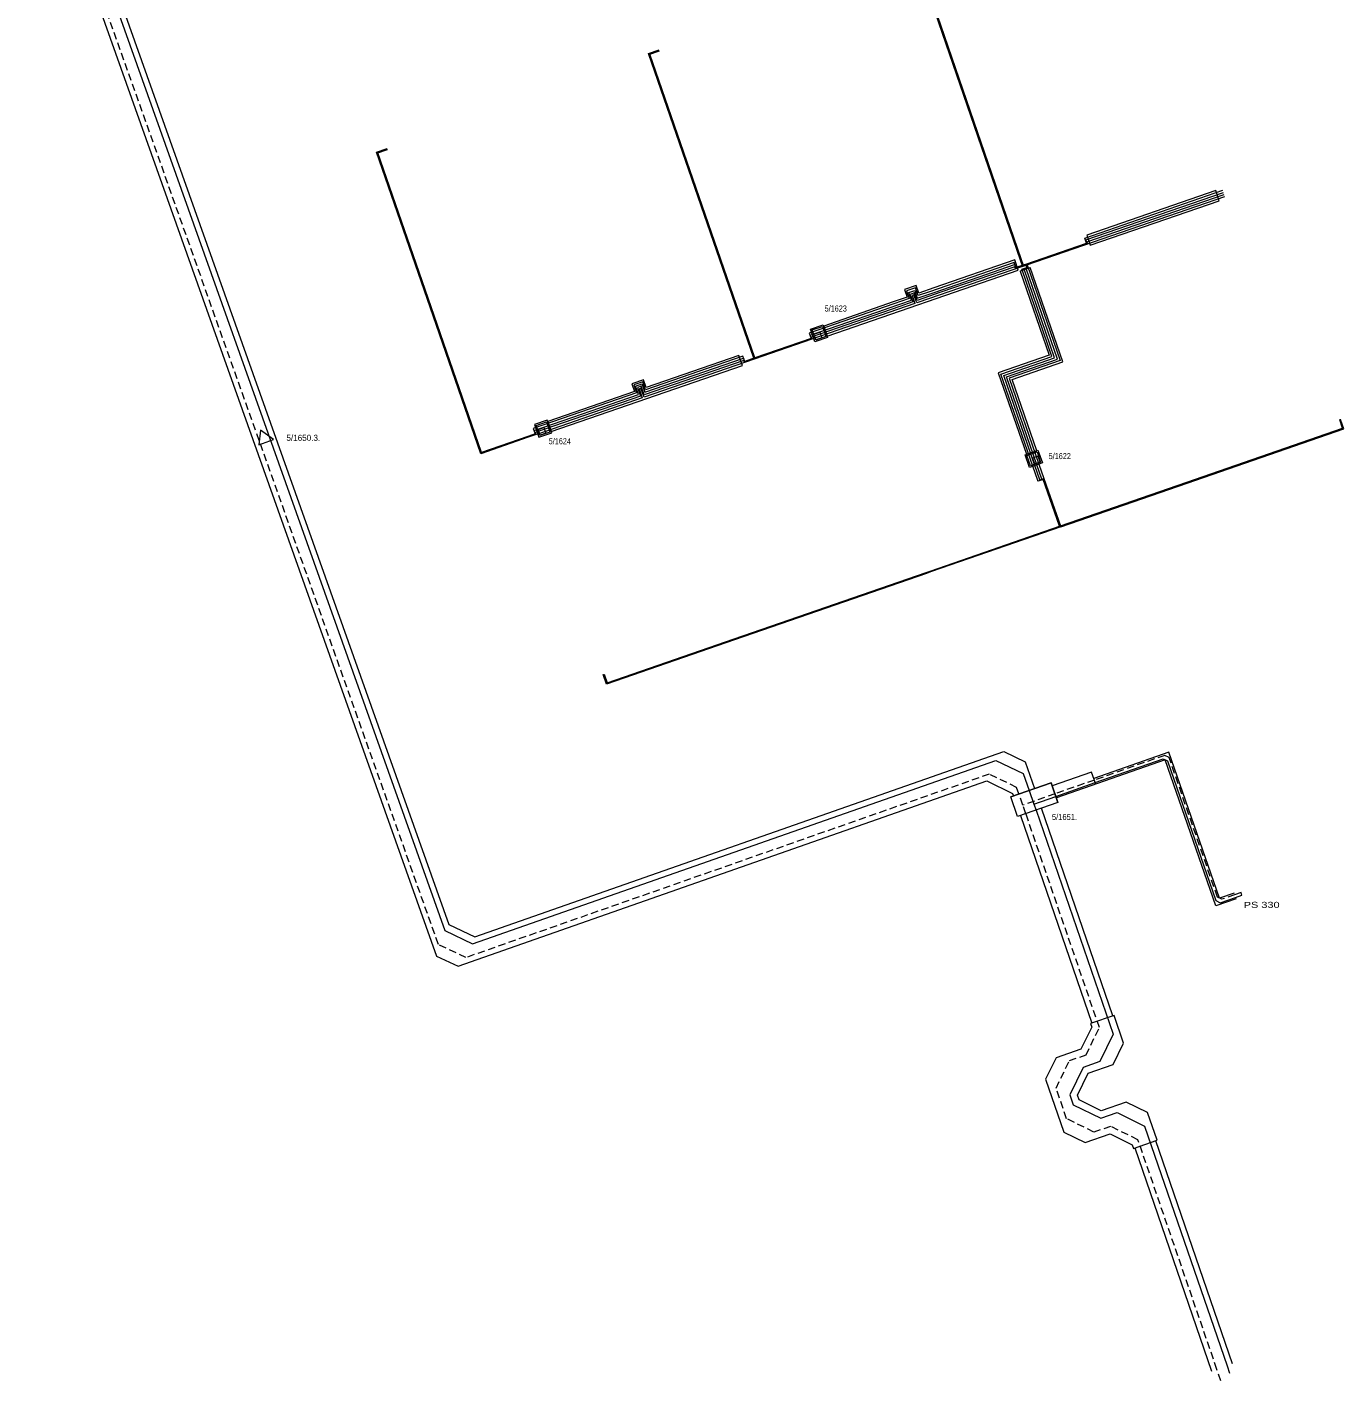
# Model space of a CAD drawing. Extents: x -473467 to -473049, y -1106745 to -1106181.
# Drawn here: x -473244.9 to -473049.3, y -1106744.6 to -1106543.7 of the extents above; entities that cross this region are included whole.
import ezdxf
from ezdxf.enums import TextEntityAlignment as Align

# ---------------------------------------------------------------- set-up
doc = ezdxf.new("R2010")
doc.units = 0
doc.header["$LTSCALE"] = 0.36
doc.linetypes.add('MEDIUM_DASHED', pattern=[4.5, 3, -1.5])
for name, color, linetype, lineweight in [('1', 7, 'MEDIUM_DASHED', 13), ('11', 7, 'Continuous', 13), ('14', 7, 'Continuous', 13), ('15', 7, 'Continuous', 13), ('17', 7, 'Continuous', 13), ('4', 7, 'Continuous', 13), ('7', 7, 'Continuous', 13)]:
    doc.layers.add(name, color=color, linetype=linetype, lineweight=lineweight)
for name, color, linetype in [('16', 7, 'Continuous'), ('6', 7, 'Continuous'), ('9', 7, 'Continuous')]:
    doc.layers.add(name, color=color, linetype=linetype)

msp = doc.modelspace()

# ---------------------------------------------------------------- linework, layer by layer
at = {"layer": '1', "linetype": 'Continuous'}
for points in [[(-473246.013, -1106500.34), (-473245.619, -1106501.193), (-473182.812, -1106677.763), (-473178.72, -1106679.719), (-473101.034, -1106652.497), (-473096.956, -1106654.459), (-473096.08, -1106656.96), (-473095.369, -1106658.988)], [(-473086.246, -1106655.792), (-473076.18, -1106652.264), (-473075.545, -1106652.572), (-473068.36, -1106673.32), (-473067.724, -1106673.628), (-473065.428, -1106672.833), (-473064.483, -1106672.506)], [(-473095.369, -1106658.988), (-473092.113, -1106657.848), (-473086.246, -1106655.792)], [(-473095.369, -1106658.988), (-473095.053, -1106659.89), (-473083.609, -1106693.153), (-473085.594, -1106697.22), (-473088.053, -1106698.065), (-473090.038, -1106702.132), (-473089.517, -1106703.647), (-473085.45, -1106705.631), (-473082.991, -1106704.786), (-473078.924, -1106706.771), (-473066.675, -1106742.375), (-473066.31, -1106743.478)]]:
    msp.add_lwpolyline(points, dxfattribs=at)
at = {"layer": '1'}
for points in [[(-473097.014, -1106659.141), (-473097.592, -1106657.49), (-473097.935, -1106656.511), (-473102.013, -1106654.549), (-473179.701, -1106681.772), (-473183.794, -1106679.815), (-473247.114, -1106501.803), (-473247.258, -1106501.495)], [(-473064.483, -1106672.506), (-473064.614, -1106672.128), (-473065.559, -1106672.455), (-473067.477, -1106673.12), (-473068.113, -1106672.811), (-473075.298, -1106652.061), (-473075.934, -1106651.754), (-473086.378, -1106655.414)], [(-473086.378, -1106655.414), (-473092.245, -1106657.47), (-473097.014, -1106659.141)], [(-473067.624, -1106744.609), (-473068.19, -1106742.899), (-473079.919, -1106708.808), (-473083.986, -1106706.823), (-473086.444, -1106707.669), (-473090.511, -1106705.684), (-473092.075, -1106701.138), (-473090.09, -1106697.071), (-473087.631, -1106696.225), (-473085.646, -1106692.158), (-473096.568, -1106660.412), (-473097.014, -1106659.141)]]:
    msp.add_lwpolyline(points, dxfattribs=at)
at = {"layer": '11'}
for p, q in [((-473096.399, -1106578.95), (-473066.993, -1106568.795)), ((-473116.063, -1106585.063), (-473116.047, -1106585.057)), ((-473128.322, -1106589.991), (-473136.906, -1106592.958)), ((-473091.387, -1106617.854), (-473072.623, -1106611.36)), ((-473139.878, -1106634.476), (-473111.357, -1106624.606)), ((-473139.864, -1106634.524), (-473111.376, -1106624.665)), ((-473111.358, -1106624.712), (-473139.85, -1106634.572)), ((-473111.337, -1106624.758), (-473139.83, -1106634.618))]:
    msp.add_line(p, q, dxfattribs=at)
for points in [[(-473115.3, -1106526.116), (-473097.408, -1106578.227), (-473097.077, -1106579.184), (-473096.718, -1106579.06), (-473096.399, -1106578.95)], [(-473115.002, -1106525.997), (-473115.258, -1106526.085), (-473097.413, -1106578.06), (-473097.361, -1106578.211), (-473097.046, -1106579.121), (-473096.74, -1106579.015), (-473096.455, -1106578.916)], [(-473114.684, -1106525.941), (-473115.194, -1106526.116), (-473097.366, -1106578.043), (-473097.314, -1106578.195), (-473097.015, -1106579.057), (-473096.761, -1106578.969), (-473096.525, -1106578.888)], [(-473114.365, -1106525.884), (-473115.131, -1106526.147), (-473097.318, -1106578.027), (-473097.266, -1106578.178), (-473096.985, -1106578.993), (-473096.766, -1106578.918), (-473096.579, -1106578.853)], [(-473136.897, -1106592.955), (-473136.947, -1106592.81), (-473152.583, -1106547.586), (-473151.024, -1106547.047)], [(-473136.867, -1106592.888), (-473136.9, -1106592.793), (-473152.519, -1106547.617), (-473151.007, -1106547.094)], [(-473136.837, -1106592.824), (-473136.853, -1106592.777), (-473152.456, -1106547.648), (-473150.991, -1106547.142)], [(-473136.806, -1106592.761), (-473152.392, -1106547.679), (-473150.975, -1106547.189)], [(-473184.561, -1106586.506), (-473192.962, -1106562.209), (-473191.402, -1106561.669)], [(-473184.511, -1106586.497), (-473192.897, -1106562.24), (-473191.385, -1106561.717)], [(-473191.369, -1106561.764), (-473192.834, -1106562.271), (-473184.463, -1106586.484)], [(-473184.413, -1106586.474), (-473192.77, -1106562.302), (-473191.353, -1106561.811)], [(-473096.579, -1106578.853), (-473087.543, -1106575.733), (-473087.808, -1106574.968), (-473067.308, -1106567.889)], [(-473096.525, -1106578.888), (-473087.48, -1106575.764), (-473087.656, -1106575.254), (-473067.204, -1106568.191)], [(-473096.455, -1106578.916), (-473087.418, -1106575.796), (-473087.505, -1106575.54), (-473067.099, -1106568.494)], [(-473096.985, -1106578.993), (-473098.05, -1106579.361), (-473098.314, -1106578.596), (-473110.877, -1106582.933), (-473112.56, -1106583.515), (-473112.954, -1106582.377), (-473114.265, -1106582.831), (-473113.873, -1106583.968), (-473116.151, -1106584.756), (-473128.732, -1106589.099)], [(-473128.58, -1106589.385), (-473117.401, -1106585.525), (-473117.024, -1106585.395), (-473113.561, -1106584.198), (-473113.953, -1106583.064), (-473113.069, -1106582.758), (-473112.676, -1106583.892), (-473111.055, -1106583.332), (-473110.033, -1106582.981), (-473098.257, -1106578.914), (-473098.081, -1106579.425), (-473097.015, -1106579.057)], [(-473097.046, -1106579.121), (-473098.112, -1106579.488), (-473098.2, -1106579.233), (-473109.189, -1106583.028), (-473112.685, -1106584.234), (-473113.077, -1106583.1), (-473113.735, -1106583.327), (-473113.34, -1106584.46), (-473115.251, -1106585.121), (-473128.428, -1106589.671)], [(-473097.077, -1106579.184), (-473112.578, -1106584.544), (-473112.766, -1106584.609), (-473113.186, -1106583.397), (-473113.465, -1106583.493), (-473113.036, -1106584.708), (-473128.322, -1106589.991)], [(-473094.757, -1106611.051), (-473094.773, -1106611.004), (-473094.79, -1106610.957), (-473095.519, -1106608.848), (-473100.258, -1106595.156), (-473092.697, -1106592.539), (-473097.124, -1106579.705), (-473097.156, -1106579.611), (-473096.395, -1106579.348), (-473096.567, -1106578.849)], [(-473094.471, -1106610.899), (-473094.487, -1106610.852), (-473095.217, -1106608.744), (-473099.851, -1106595.353), (-473092.29, -1106592.737), (-473096.824, -1106579.602), (-473096.84, -1106579.554), (-473096.332, -1106579.379), (-473096.504, -1106578.88)], [(-473094.185, -1106610.747), (-473094.914, -1106608.639), (-473099.444, -1106595.551), (-473091.884, -1106592.935), (-473096.524, -1106579.498), (-473096.268, -1106579.41), (-473096.44, -1106578.911)], [(-473096.377, -1106578.942), (-473091.477, -1106593.133), (-473099.037, -1106595.749), (-473094.612, -1106608.534), (-473093.882, -1106610.643)], [(-473169.289, -1106604.151), (-473170.443, -1106604.55), (-473177.481, -1106606.983), (-473184.561, -1106586.506)], [(-473169.309, -1106604.104), (-473170.46, -1106604.502), (-473177.45, -1106606.919), (-473184.511, -1106586.497)], [(-473184.463, -1106586.484), (-473177.419, -1106606.855), (-473170.476, -1106604.455), (-473169.373, -1106604.073)], [(-473169.436, -1106604.042), (-473170.492, -1106604.407), (-473177.388, -1106606.792), (-473184.413, -1106586.474)], [(-473128.428, -1106589.671), (-473128.336, -1106589.938), (-473136.87, -1106592.889)], [(-473136.843, -1106592.826), (-473128.399, -1106589.907), (-473128.58, -1106589.385)], [(-473128.732, -1106589.099), (-473128.463, -1106589.876), (-473136.809, -1106592.762)], [(-473136.809, -1106592.762), (-473138.293, -1106593.275), (-473138.562, -1106592.494), (-473153.043, -1106597.495), (-473153.455, -1106596.301), (-473154.778, -1106596.761), (-473154.366, -1106597.951), (-473169.71, -1106603.25), (-473169.436, -1106604.042)], [(-473169.373, -1106604.073), (-473169.558, -1106603.536), (-473154.073, -1106598.189), (-473154.503, -1106596.942), (-473153.558, -1106596.616), (-473153.128, -1106597.862), (-473138.505, -1106592.813), (-473138.324, -1106593.338), (-473136.843, -1106592.826)], [(-473136.87, -1106592.889), (-473138.355, -1106593.402), (-473138.448, -1106593.132), (-473153.212, -1106598.23), (-473153.659, -1106596.936), (-473154.226, -1106597.132), (-473153.779, -1106598.426), (-473169.407, -1106603.822), (-473169.309, -1106604.104)], [(-473136.906, -1106592.958), (-473153.241, -1106598.604), (-473153.715, -1106597.233), (-473153.999, -1106597.331), (-473153.525, -1106598.702), (-473169.025, -1106604.059), (-473169.289, -1106604.151)], [(-473072.623, -1106611.36), (-473049.334, -1106603.301), (-473049.824, -1106601.883)], [(-473072.669, -1106611.217), (-473049.525, -1106603.208), (-473049.966, -1106601.932)], [(-473072.656, -1106611.266), (-473049.461, -1106603.239), (-473049.919, -1106601.916)], [(-473072.638, -1106611.313), (-473049.397, -1106603.27), (-473049.872, -1106601.899)], [(-473111.376, -1106624.665), (-473110.598, -1106624.396), (-473091.514, -1106617.792), (-473093.961, -1106610.723), (-473094.471, -1106610.899)], [(-473094.185, -1106610.747), (-473093.93, -1106610.659), (-473093.93, -1106610.659), (-473091.45, -1106617.823), (-473110.575, -1106624.441), (-473111.358, -1106624.712)], [(-473111.357, -1106624.606), (-473110.613, -1106624.348), (-473091.578, -1106617.761), (-473093.991, -1106610.786), (-473094.757, -1106611.051)], [(-473093.882, -1106610.643), (-473091.387, -1106617.854), (-473110.562, -1106624.489), (-473111.337, -1106624.758)], [(-473091.578, -1106617.761), (-473091.436, -1106617.712), (-473072.669, -1106611.217)], [(-473091.514, -1106617.792), (-473091.42, -1106617.759), (-473072.656, -1106611.266)], [(-473091.45, -1106617.823), (-473091.403, -1106617.806), (-473072.638, -1106611.313)], [(-473139.83, -1106634.618), (-473158.826, -1106641.192), (-473159.317, -1106639.774)], [(-473139.85, -1106634.572), (-473158.796, -1106641.128), (-473159.27, -1106639.758)], [(-473159.223, -1106639.742), (-473158.765, -1106641.065), (-473139.864, -1106634.524)], [(-473159.175, -1106639.725), (-473158.734, -1106641.001), (-473139.878, -1106634.476)]]:
    msp.add_lwpolyline(points, dxfattribs=at)
at = {"layer": '14'}
for points in [[(-473126.765, -1106588.094), (-473126.245, -1106589.607), (-473127.757, -1106590.13), (-473128.279, -1106588.618), (-473126.762, -1106588.093)], [(-473169.255, -1106602.784), (-473167.739, -1106602.261), (-473167.219, -1106603.763), (-473168.728, -1106604.294), (-473169.255, -1106602.784)], [(-473095.878, -1106608.761), (-473096.401, -1106607.249), (-473094.889, -1106606.726), (-473094.366, -1106608.238)]]:
    msp.add_lwpolyline(points, close=True, dxfattribs=at)
at = {"layer": '15'}
for points in [[(-473128.02, -1106589.216), (-473127.17, -1106588.922), (-473126.876, -1106589.772), (-473127.726, -1106590.067), (-473128.02, -1106589.216)], [(-473168.697, -1106604.23), (-473168.996, -1106603.382), (-473168.147, -1106603.083), (-473167.848, -1106603.931)], [(-473094.43, -1106608.207), (-473094.724, -1106607.356), (-473095.574, -1106607.651), (-473095.28, -1106608.501)]]:
    msp.add_lwpolyline(points, close=True, dxfattribs=at)
at = {"layer": '17'}
for points in [[(-473087.006, -1106576.041), (-473067.836, -1106569.425), (-473068.358, -1106567.913), (-473087.528, -1106574.528)], [(-473116.253, -1106584.46), (-473126.579, -1106588.03), (-473126.056, -1106589.542), (-473097.681, -1106579.732), (-473098.204, -1106578.219), (-473110.241, -1106582.381), (-473112.474, -1106583.153), (-473112.867, -1106582.019), (-473114.568, -1106582.607), (-473114.176, -1106583.742)], [(-473127.881, -1106590.385), (-473128.534, -1106588.494), (-473126.644, -1106587.841), (-473125.991, -1106589.731)], [(-473138.857, -1106593.227), (-473139.163, -1106592.381), (-473152.951, -1106597.148), (-473153.343, -1106596.014), (-473155.045, -1106596.602), (-473154.653, -1106597.736), (-473167.558, -1106602.197), (-473167.026, -1106603.707), (-473138.62, -1106593.886)], [(-473168.85, -1106604.549), (-473166.964, -1106603.885), (-473167.628, -1106601.998), (-473169.514, -1106602.663)], [(-473096.656, -1106607.125), (-473094.766, -1106606.471), (-473094.112, -1106608.361), (-473096.002, -1106609.015)]]:
    msp.add_lwpolyline(points, close=True, dxfattribs=at)
for points in [[(-473097.409, -1106579.873), (-473097.409, -1106579.873), (-473093.093, -1106592.347), (-473100.653, -1106594.964), (-473096.466, -1106607.06), (-473094.955, -1106606.537), (-473098.617, -1106595.952), (-473091.057, -1106593.336), (-473095.897, -1106579.35), (-473095.897, -1106579.35)], [(-473096.653, -1106579.612), (-473097.409, -1106579.873), (-473096.653, -1106579.612), (-473095.897, -1106579.35)]]:
    msp.add_lwpolyline(points, dxfattribs=at)
at = {"layer": '4'}
for points in [[(-473210.471, -1106605.678), (-473208.253, -1106604.885), (-473210.201, -1106603.476)], [(-473098.816, -1106657.919), (-473092.823, -1106655.819), (-473091.798, -1106658.745), (-473097.791, -1106660.845)]]:
    msp.add_lwpolyline(points, close=True, dxfattribs=at)
at = {"layer": '7'}
for p, q in [((-473092.823, -1106655.819), (-473098.816, -1106657.919)), ((-473092.823, -1106655.819), (-473098.816, -1106657.919)), ((-473091.798, -1106658.745), (-473092.823, -1106655.819)), ((-473091.798, -1106658.745), (-473092.823, -1106655.819)), ((-473086.791, -1106654.234), (-473092.658, -1106656.29)), ((-473086.791, -1106654.234), (-473092.658, -1106656.29)), ((-473086.163, -1106656.027), (-473086.791, -1106654.234)), ((-473086.163, -1106656.027), (-473086.791, -1106654.234)), ((-473097.791, -1106660.845), (-473098.816, -1106657.919)), ((-473091.798, -1106658.745), (-473097.791, -1106660.845)), ((-473091.798, -1106658.745), (-473097.791, -1106660.845)), ((-473083.651, -1106690.418), (-473094.248, -1106659.613)), ((-473097.366, -1106660.695), (-473097.369, -1106660.687)), ((-473097.366, -1106660.695), (-473086.771, -1106691.492)), ((-473080.395, -1106710.025), (-473068.988, -1106743.183)), ((-473065.873, -1106742.093), (-473077.274, -1106708.952))]:
    msp.add_line(p, q, dxfattribs=at)
for points in [[(-473244.636, -1106501.418), (-473182.228, -1106676.869), (-473178.391, -1106678.703), (-473099.852, -1106651.182), (-473096.666, -1106652.715), (-473095.277, -1106656.679)], [(-473247.638, -1106502.809), (-473184.069, -1106681.541), (-473180.872, -1106683.069), (-473102.347, -1106655.553), (-473098.524, -1106657.393), (-473098.392, -1106657.77)], [(-473065.641, -1106672.219), (-473067.795, -1106672.965), (-473075.308, -1106651.27), (-473086.463, -1106655.179)], [(-473065.346, -1106673.07), (-473068.351, -1106674.11), (-473075.862, -1106652.418), (-473092.03, -1106658.083)]]:
    msp.add_lwpolyline(points, dxfattribs=at)
msp.add_lwpolyline([(-473086.96, -1106691.557), (-473086.771, -1106692.106), (-473088.382, -1106695.377), (-473092.082, -1106696.65), (-473093.633, -1106699.827), (-473090.933, -1106707.676), (-473087.755, -1106709.226), (-473084.055, -1106707.953), (-473080.767, -1106709.558), (-473080.584, -1106710.09), (-473077.085, -1106708.887), (-473078.5, -1106704.773), (-473081.678, -1106703.223), (-473085.38, -1106704.496), (-473088.665, -1106702.893), (-473088.903, -1106702.202), (-473087.3, -1106698.917), (-473083.597, -1106697.644), (-473082.046, -1106694.466), (-473083.462, -1106690.353)], close=True, dxfattribs=at)

# ---------------------------------------------------------------- texts
at = {"layer": '16', "width": 0.75}
for s, p in [('5/1623', (-473126.438, -1106585.881)), ('5/1624', (-473167.405, -1106605.579)), ('5/1622', (-473093.176, -1106607.783))]:
    msp.add_text(s, height=0.9, dxfattribs=at).set_placement(p)
at = {"layer": '6'}
msp.add_text('5/1650.3.', height=0.9, dxfattribs=at).set_placement((-473206.352, -1106605.073))
at = {"layer": '6', "width": 0.9}
msp.add_text('5/1651.', height=0.9, dxfattribs=at).set_placement((-473092.689, -1106661.35))
at = {"layer": '9', "width": 1.35}
msp.add_text('PS 330', height=0.9, dxfattribs=at).set_placement((-473061.549, -1106674.399), align=Align.CENTER)

doc.saveas('drawing.dxf')
